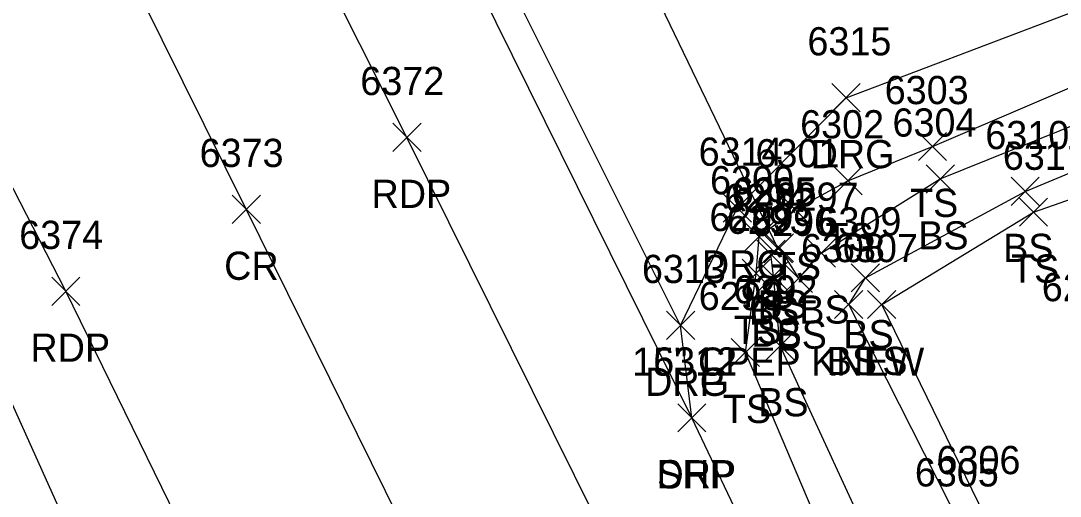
# Model space of a CAD drawing. Extents: x 1439173 to 1457902, y 641926 to 659889.
# Drawn here: x 1448963.4 to 1449037.1, y 643527.6 to 643561.3 of the extents above; entities that cross this region are included whole.
import ezdxf

# ---------------------------------------------------------------- set-up
doc = ezdxf.new("R2010")
doc.units = 0
for name, color, linetype in [('D_A', 7, 'Continuous'), ('D_C', 7, 'Continuous'), ('D_I', 7, 'Continuous'), ('D_TIC', 7, 'Continuous'), ('DCP', 7, 'Continuous'), ('L_A', 7, 'Continuous'), ('L_I', 7, 'Continuous'), ('L_TIC', 7, 'Continuous'), ('LELB', 7, 'Continuous'), ('P_A', 7, 'Continuous'), ('P_I', 7, 'Continuous'), ('P_TIC', 7, 'Continuous'), ('PET', 7, 'Continuous'), ('PRC', 7, 'Continuous'), ('PSP', 7, 'Continuous'), ('R_A', 7, 'Continuous'), ('R_I', 7, 'Continuous'), ('R_TIC', 7, 'Continuous'), ('RDG', 7, 'Continuous'), ('RDP', 7, 'Continuous')]:
    doc.layers.add(name, color=color, linetype=linetype)

msp = doc.modelspace()

# ---------------------------------------------------------------- linework, layer by layer
at = {"layer": 'D_TIC'}
for points in [[(1449016.133, 643544.14), (1449018.133, 643546.14)], [(1449018.133, 643544.14), (1449016.133, 643546.14)]]:
    msp.add_lwpolyline(points, dxfattribs=at)
at = {"layer": 'DCP'}
msp.add_lwpolyline([(1449017.133, 643545.14), (1449003.398, 643573.642)], dxfattribs=at)
at = {"layer": 'L_TIC'}
for points in [[(1449027.067, 643551.393), (1449029.067, 643553.393)], [(1449029.067, 643551.393), (1449027.067, 643553.393)], [(1449021.072, 643548.965), (1449023.072, 643550.965)], [(1449023.072, 643548.965), (1449021.072, 643550.965)], [(1449027.618, 643549.09), (1449029.618, 643551.09)], [(1449029.618, 643549.09), (1449027.618, 643551.09)], [(1449033.639, 643548.205), (1449035.639, 643550.205)], [(1449035.639, 643548.205), (1449033.639, 643550.205)], [(1449017.338, 643546.913), (1449019.338, 643548.913)], [(1449019.338, 643546.913), (1449017.338, 643548.913)], [(1449034.229, 643546.736), (1449036.229, 643548.736)], [(1449036.229, 643546.736), (1449034.229, 643548.736)], [(1449014.77, 643545.004), (1449016.77, 643547.004)], [(1449016.77, 643545.004), (1449014.77, 643547.004)], [(1449016.215, 643544.204), (1449018.215, 643546.204)], [(1449018.215, 643544.204), (1449016.215, 643546.204)], [(1449015.617, 643543.748), (1449017.617, 643545.748)], [(1449017.617, 643543.748), (1449015.617, 643545.748)], [(1449019.185, 643543.837), (1449021.185, 643545.837)], [(1449021.185, 643543.837), (1449019.185, 643545.837)], [(1449014.569, 643542.393), (1449016.569, 643544.393)], [(1449016.569, 643542.393), (1449014.569, 643544.393)], [(1449015.788, 643542.195), (1449017.788, 643544.195)], [(1449017.788, 643542.195), (1449015.788, 643544.195)], [(1449017.572, 643542.051), (1449019.572, 643544.051)], [(1449019.572, 643542.051), (1449017.572, 643544.051)], [(1449022.308, 643542.084), (1449024.308, 643544.084)], [(1449024.308, 643542.084), (1449022.308, 643544.084)], [(1449021.128, 643540.187), (1449023.128, 643542.187)], [(1449023.128, 643540.187), (1449021.128, 643542.187)], [(1449023.471, 643540.191), (1449025.471, 643542.191)], [(1449025.471, 643540.191), (1449023.471, 643542.191)], [(1449016.268, 643537.262), (1449018.268, 643539.262)], [(1449018.268, 643537.262), (1449016.268, 643539.262)], [(1449013.8, 643536.788), (1449015.8, 643538.788)], [(1449015.8, 643536.788), (1449013.8, 643538.788)]]:
    msp.add_lwpolyline(points, dxfattribs=at)
at = {"layer": 'LELB'}
for points in [[(1449172.576, 643496.468), (1449129.213, 643485.499), (1449108.733, 643481.403), (1449076.572, 643475.292), (1449069.889, 643474.136), (1449066.379, 643472.306), (1449055.003, 643473.16), (1449052.284, 643472.717), (1449049.433, 643470.953), (1449040.04, 643491.115), (1449024.709, 643522.119), (1449017.268, 643538.262), (1449016.788, 643543.195), (1449016.617, 643544.748), (1449017.215, 643545.204), (1449018.572, 643543.051), (1449020.185, 643544.837), (1449028.618, 643550.09), (1449057.663, 643561.796), (1449085.701, 643571.204), (1449125.573, 643582.299), (1449170.283, 643591.556)], [(1449052.284, 643472.717), (1449044.67, 643493.195), (1449030.205, 643525.289), (1449022.128, 643541.187), (1449023.308, 643543.084), (1449034.639, 643549.205), (1449058.077, 643558.958), (1449086.882, 643566.744), (1449127.06, 643578.044), (1449171.013, 643587.094)], [(1449067.537, 643468.948), (1449054.133, 643467.182), (1449048.159, 643469.685), (1449036.681, 643490.401), (1449022.126, 643520.527), (1449014.8, 643537.788), (1449015.569, 643543.393), (1449015.77, 643546.004), (1449018.338, 643547.913), (1449022.072, 643549.965), (1449028.067, 643552.393), (1449057.158, 643564.872), (1449083.62, 643574.776)], [(1449048.159, 643469.685), (1449052.141, 643469.916), (1449055.003, 643473.16), (1449046.764, 643493.535), (1449031.794, 643526.161), (1449024.471, 643541.191), (1449035.229, 643547.736), (1449058.907, 643556.037), (1449087.496, 643565.295)]]:
    msp.add_lwpolyline(points, dxfattribs=at)
at = {"layer": 'P_TIC'}
for points in [[(1448989.81, 643552.035), (1448991.81, 643554.035)], [(1448991.81, 643552.035), (1448989.81, 643554.035)], [(1448978.417, 643546.937), (1448980.417, 643548.937)], [(1448980.417, 643546.937), (1448978.417, 643548.937)], [(1448965.627, 643541.125), (1448967.627, 643543.125)], [(1448967.627, 643541.125), (1448965.627, 643543.125)], [(1449010.01, 643532.154), (1449012.01, 643534.154)], [(1449012.01, 643532.154), (1449010.01, 643534.154)]]:
    msp.add_lwpolyline(points, dxfattribs=at)
at = {"layer": 'PET'}
for points in [[(1449162.581, 643198.272), (1449141.478, 643242.395), (1449121.689, 643284.019), (1449089.798, 643350.471), (1449063.608, 643404.763), (1449045.086, 643442.414), (1449024.862, 643484.454), (1449010.101, 643514.114), (1448990.81, 643553.035), (1448970.838, 643592.715), (1448947.224, 643637.956), (1448929.605, 643671.834), (1448913.026, 643703.205), (1448880.265, 643765.401), (1448860.142, 643803.648), (1448849.295, 643824.32), (1448831.931, 643856.996), (1448813.546, 643891.177), (1448792.864, 643930.507), (1448774.914, 643964.184), (1448756.706, 643999.716), (1448741.681, 644029.904), (1448721.663, 644072.108)], [(1449139.974, 643188.126), (1449117.597, 643232.767), (1449099.108, 643273.199), (1449066.342, 643340.972), (1449039.441, 643395.715), (1449020.72, 643432.948), (1449000.265, 643474.215), (1448984.453, 643505.698), (1448966.627, 643542.125), (1448946.778, 643580.795), (1448923.535, 643626.671), (1448906.333, 643660.758), (1448890.573, 643691.551), (1448882.774, 643706.141), (1448861.662, 643747.378), (1448842.888, 643782.499), (1448829.181, 643808.282), (1448815.052, 643835.061), (1448764.915, 643929.878), (1448739.21, 643978.475), (1448719.136, 644017.804), (1448697.573, 644061.644)]]:
    msp.add_lwpolyline(points, dxfattribs=at)
at = {"layer": 'PRC'}
msp.add_lwpolyline([(1449151.129, 643193.264), (1449129.917, 643237.179), (1449110.209, 643278.66), (1449077.821, 643346.328), (1449052.307, 643400.081), (1449033.568, 643437.636), (1449013.307, 643480.221), (1448998.166, 643509.98), (1448979.417, 643547.937), (1448959.999, 643587.026), (1448936.541, 643632.544), (1448918.641, 643666.677), (1448902.118, 643697.964), (1448893.713, 643713.684), (1448873.044, 643753.326), (1448854.508, 643788.551), (1448840.553, 643814.737), (1448825.904, 643842.483), (1448798.392, 643894.2), (1448777.046, 643935.058), (1448750.784, 643985.196), (1448731.141, 644023.278), (1448710.458, 644067.889)], dxfattribs=at)
at = {"layer": 'PSP'}
for points in [[(1449169.824, 643203.272), (1449149.928, 643245.983), (1449130.544, 643285.723), (1449118.385, 643311.339), (1449097.457, 643354.399), (1449071.884, 643407.834), (1449056.011, 643441.145), (1449042.625, 643467.591), (1449032.608, 643488.349), (1449017.969, 643518.511), (1449011.01, 643533.154), (1448991.339, 643572.892), (1448977.119, 643597.858), (1448952.223, 643640.32)], [(1449131.438, 643184.414), (1449109.558, 643229.091), (1449090.455, 643269.75), (1449065.763, 643321.33), (1449053.102, 643346.176), (1449034.828, 643384.262), (1449031.471, 643392.522), (1449012.983, 643429.546), (1448992.544, 643471.256), (1448985.017, 643487.755), (1448974.422, 643508.354), (1448960.29, 643539.718), (1448943.457, 643579.586), (1448921.836, 643625.914)]]:
    msp.add_lwpolyline(points, dxfattribs=at)
at = {"layer": 'R_TIC'}
for points in [[(1449020.942, 643554.85), (1449022.942, 643556.85)], [(1449022.942, 643554.85), (1449020.942, 643556.85)], [(1449013.229, 643547.025), (1449015.229, 643549.025)], [(1449015.229, 643547.025), (1449013.229, 643549.025)], [(1449009.209, 643538.711), (1449011.209, 643540.711)], [(1449011.209, 643538.711), (1449009.209, 643540.711)], [(1449009.209, 643538.711), (1449011.209, 643540.711)], [(1449011.209, 643538.711), (1449009.209, 643540.711)], [(1449010.01, 643532.154), (1449012.01, 643534.154)], [(1449012.01, 643532.154), (1449010.01, 643534.154)]]:
    msp.add_lwpolyline(points, dxfattribs=at)
at = {"layer": 'RDG'}
msp.add_lwpolyline([(1449010.209, 643539.711), (1449014.229, 643548.025), (1449021.942, 643555.85), (1449056.857, 643569.101), (1449083.131, 643577.506), (1449124.56, 643587.451), (1449167.438, 643600.135)], dxfattribs=at)
at = {"layer": 'RDP'}
msp.add_lwpolyline([(1449011.01, 643533.154), (1449010.209, 643539.711), (1448995.244, 643569.638), (1448991.339, 643572.892)], dxfattribs=at)

# ---------------------------------------------------------------- texts
at = {"layer": 'D_A'}
msp.add_text('P', height=2, dxfattribs=at).set_placement((1449016.511, 643540.14))
at = {"layer": 'D_C'}
msp.add_text('15" CPEP KNEW', height=2, dxfattribs=at).set_placement((1449006.771, 643536.14))
at = {"layer": 'D_I'}
msp.add_text('6355', height=2, dxfattribs=at).set_placement((1449013.826, 643548.14))
at = {"layer": 'L_A'}
for s, p in [('TS', (1449026.477, 643547.393)), ('TS', (1449020.481, 643544.965)), ('BS', (1449027.059, 643545.09)), ('BS', (1449033.08, 643544.205)), ('TS', (1449016.747, 643542.913)), ('TS', (1449033.638, 643542.736)), ('TS', (1449014.179, 643541.004)), ('BS', (1449015.058, 643539.748)), ('BS', (1449015.656, 643540.204)), ('BS', (1449018.626, 643539.837)), ('TS', (1449013.978, 643538.393)), ('BS', (1449015.229, 643538.195)), ('BS', (1449017.013, 643538.051)), ('BS', (1449021.749, 643538.084)), ('BS', (1449020.569, 643536.187)), ('TS', (1449022.88, 643536.191)), ('BS', (1449015.709, 643533.262)), ('TS', (1449013.209, 643532.788))]:
    msp.add_text(s, height=2, dxfattribs=at).set_placement(p)
at = {"layer": 'L_I'}
for s, p in [('6303', (1449024.681, 643555.393)), ('6304', (1449025.232, 643553.09)), ('6302', (1449018.686, 643552.965)), ('6310', (1449031.812, 643552.205)), ('6301', (1449015.519, 643550.913)), ('6311', (1449033.055, 643550.736)), ('6300', (1449012.297, 643549.004)), ('6295', (1449013.908, 643548.204)), ('6294', (1449013.31, 643547.748)), ('6297', (1449016.878, 643547.837)), ('6299', (1449012.254, 643546.393)), ('6293', (1449013.481, 643546.195)), ('6296', (1449015.21, 643546.051)), ('6309', (1449019.914, 643546.084)), ('6308', (1449018.742, 643544.187)), ('6307', (1449021.085, 643544.191)), ('6292', (1449013.961, 643541.262)), ('6223', (1449035.818, 643541.423)), ('6223', (1449035.818, 643541.423)), ('6298', (1449011.493, 643540.788)), ('6306', (1449028.353, 643529.161)), ('6305', (1449026.819, 643528.289))]:
    msp.add_text(s, height=2, dxfattribs=at).set_placement(p)
at = {"layer": 'P_A'}
for s, p in [('RDP', (1448988.299, 643548.035)), ('CR', (1448977.85, 643542.937)), ('RDP', (1448964.115, 643537.125)), ('SHP', (1449008.545, 643528.154))]:
    msp.add_text(s, height=2, dxfattribs=at).set_placement(p)
at = {"layer": 'P_I'}
for s, p in [('6372', (1448987.503, 643556.035)), ('6373', (1448976.11, 643550.937)), ('6374', (1448963.32, 643545.125)), ('6312', (1449008.27, 643536.154))]:
    msp.add_text(s, height=2, dxfattribs=at).set_placement(p)
at = {"layer": 'R_A'}
for s, p in [('DRG', (1449019.431, 643550.85)), ('DRG', (1449011.717, 643543.025)), ('DRG', (1449007.697, 643534.711)), ('DRP', (1449007.697, 643534.711)), ('DRP', (1449008.498, 643528.154))]:
    msp.add_text(s, height=2, dxfattribs=at).set_placement(p)
at = {"layer": 'R_I'}
for s, p in [('6315', (1449019.202, 643558.85)), ('6314', (1449011.488, 643551.025)), ('6313', (1449007.469, 643542.711)), ('6313', (1449007.469, 643542.711)), ('6312', (1449008.27, 643536.154))]:
    msp.add_text(s, height=2, dxfattribs=at).set_placement(p)

doc.saveas('drawing.dxf')
